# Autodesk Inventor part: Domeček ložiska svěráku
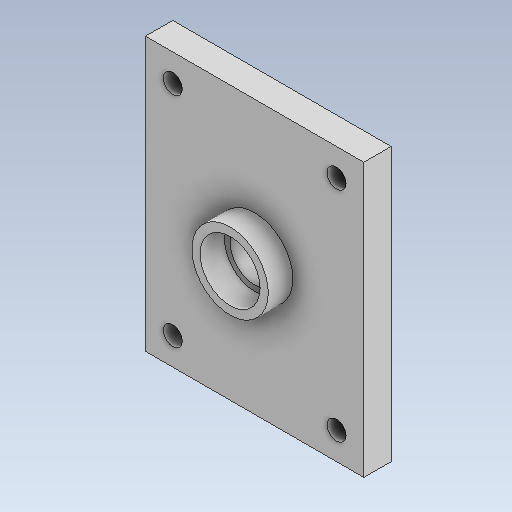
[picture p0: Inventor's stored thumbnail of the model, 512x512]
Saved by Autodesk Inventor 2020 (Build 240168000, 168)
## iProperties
Created: 2025-03
Part Number: Domeček ložiska svěráku
Material: Všeobecné
Document SubType Name: Modeling
Designer: doma
Density: 1 g/cm^3
Appearance: Výchozí
Mass: 78.0365 g
Surface Area: 216.42 cm^2
Volume: 78.0365 cm^3
Author: doma
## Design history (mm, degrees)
sketch "Náčrt1"
  geometry: L1 (-40, -50)-(40, -50); L2 (40, -50)-(40, 50); L3 (40, 50)-(-40, 50); L4 (-40, 50)-(-40, -50); L5 (-40, -50)-(40, 50); L6 (40, -50)-(-40, 50); C1 r 9 at (0, 0); 1 further point
  constraints: 12 end point, 2 midpoint, 2 parallel, 1 centre point, 1 coincident, 1 horizontal, 1 perpendicular
  dimensions: "d0" = 80 distance of L3.end L2.end; "d1" = 100 distance of L2.end L1.end; "d2" = 18 diameter of C1
extrude "Vysunutí1" new body sketch "Náčrt1" distance "d3" = 10; taper "d4" = 0 deg
sketch "Náčrt2"
  geometry: C1 r 14 at (0, 0); C2 r 11 at (0, 0); 1 further point
  constraints: 2 centre point, 2 coincident
  dimensions: "d5" = 28 diameter of C1; "d6" = 22 diameter of C2
extrude "Vysunutí2" join sketch "Náčrt2" distance "d7" = 9; taper "d8" = 0 deg
sketch "Náčrt4"
  geometry: L1 (40, -50)-(-40, -50) reference; L2 (40, 50)-(40, -50) reference; 5 further points
  constraints: 1 horizontal, 1 vertical, 3 other
  dimensions: "d12" = 10 distance from line of L1 point (30, -40); "d13" = 10 distance from line of L2 point (30, -40); "d16" = 60 distance of point (30, -40) point (-30, -40); "d19" = 80 distance of point (30, -40) point (30, 40)
hole "Díra1" sketch "Náčrt4" at (30, -40), (-30, -40), (30, 40), (-30, 40) diameter "d22" = 7; stored, may be unused: countersink angle "d26" = 90 deg, drill point angle "d28" = 118 deg; dims "d23" = 12, "d24" = 4, "d25" = 2, "d27" = 17.1
node "Těleso1"
